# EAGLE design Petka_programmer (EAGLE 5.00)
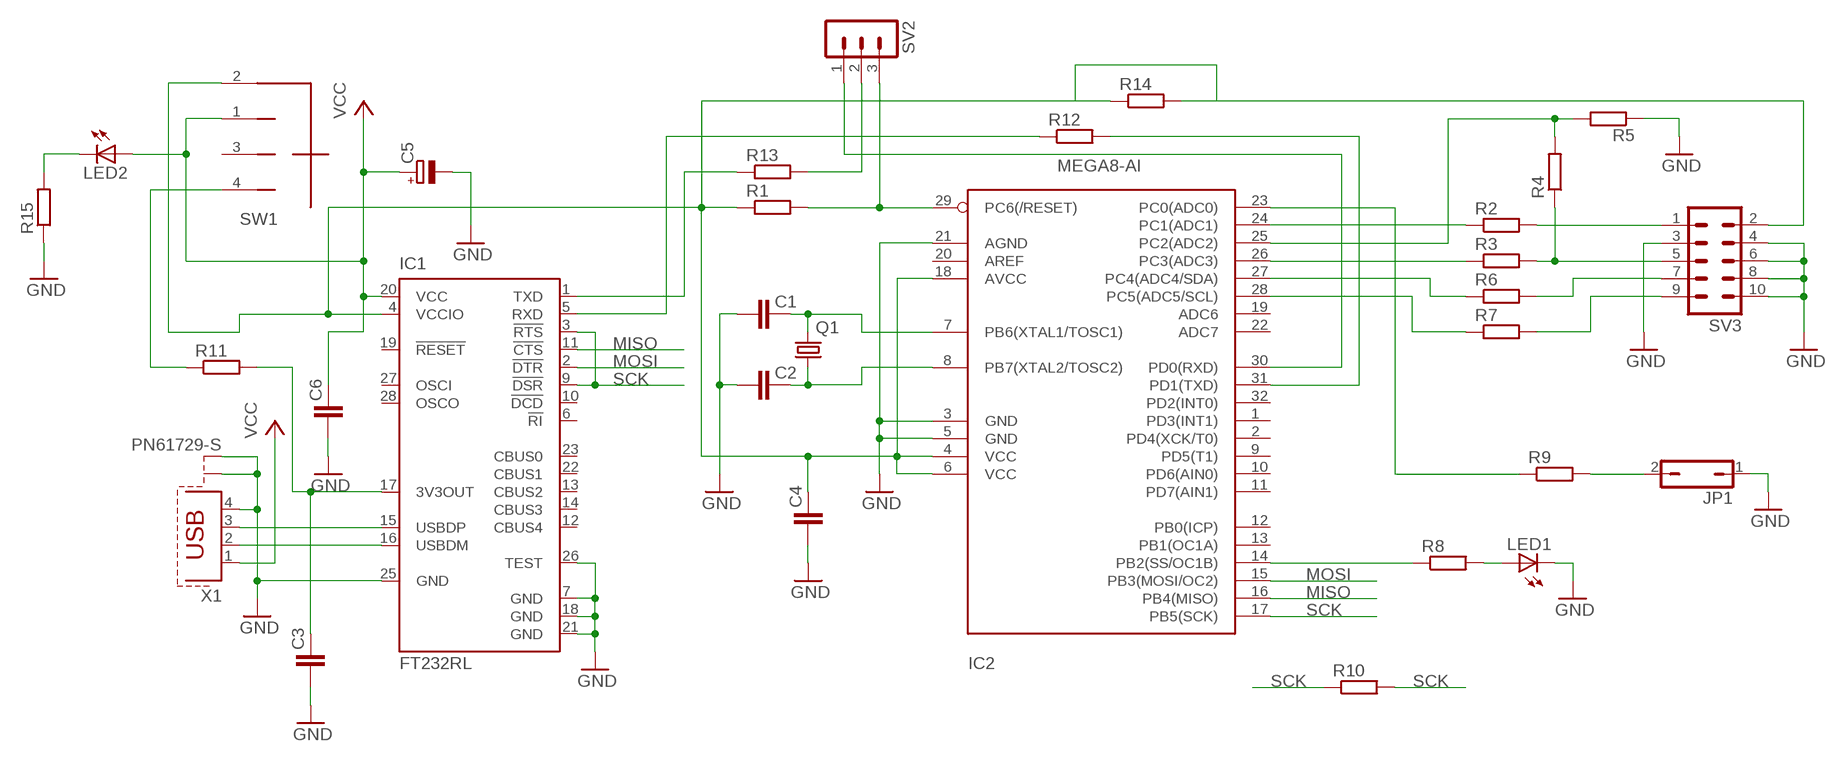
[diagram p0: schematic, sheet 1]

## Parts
C1  C-EUC0805  [C0805]
C2  C-EUC0805  [C0805]
C3  C-EUC0805  [C0805]
C4  C-EUC0805  [C0805]
C5  CPOL-EUSMCD  [SMC_D]
C6  C-EUC0805  [C0805]
IC1  FT232RL  [SSOP28]
IC2  MEGA8-AI  [TQFP32-08]
JP1  JP1Q  [JP1]
LED1  LEDCHIPLED_0805  [CHIPLED_0805]
LED2  LEDCHIPLED_0805  [CHIPLED_0805]
Q1  CRYSTALHC49S  [HC49/S]
R1  R-EU_R0805  [R0805]
R2  R-EU_R0805  [R0805]
R3  R-EU_R0805  [R0805]
R4  R-EU_R0805  [R0805]
R5  R-EU_R0805  [R0805]
R6  R-EU_R0805  [R0805]
R7  R-EU_R0805  [R0805]
R8  R-EU_R0805  [R0805]
R9  R-EU_R0805  [R0805]
R10  R-EU_R0805  [R0805]
R11  R-EU_R0805  [R0805]
R12  R-EU_R0805  [R0805]
R13  R-EU_R0805  [R0805]
R14  R-EU_R0805  [R0805]
R15  R-EU_R0805  [R0805]
SV2  MA03-1  [MA03-1]
SV3  MA05-2  [MA05-2]
SW1  SWITCH1  [SWITCH1]
X1  PN61729-S  [PN61729-S]

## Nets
GND: C1.1 C2.1 C3.1 C4.1 C5.- C6.1 IC1.7(GND) IC1.18(GND) IC1.21(GND) IC1.25(GND) IC1.26(TEST) IC2.3(GND) IC2.5(GND) IC2.21(AGND) JP1.1 LED1.C R5.1 R15.1 SV3.3 SV3.4 SV3.6 SV3.8 SV3.10 X1.4 X1.S1 X1.S2
MISO: IC1.11(!CTS) IC2.16(PB4(MISO))
MOSI: IC1.2(!DTR) IC2.15(PB3(MOSI/OC2))
N$1: LED2.C R15.2
N$2: IC2.29(PC6(/RESET)) R1.2 SV2.3
N$3: IC1.1(TXD) R13.1
N$4: IC2.30(PD0(RXD)) SV2.1
N$5: IC1.5(RXD) R12.1
N$6: C2.2 IC2.8(PB7(XTAL2/TOSC2)) Q1.1
N$7: C1.2 IC2.7(PB6(XTAL1/TOSC1)) Q1.2
N$8: IC1.16(USBDM) X1.2
N$9: IC1.15(USBDP) X1.3
N$10: R11.1 SW1.4
N$11: R2.2 SV3.1
N$12: IC2.24(PC1(ADC1)) R2.1
N$13: IC2.25(PC2(ADC2)) R4.2 R5.2
N$14: R3.2 R4.1 SV3.5
N$15: IC2.26(PC3(ADC3)) R3.1
N$16: R7.2 SV3.9
N$17: R6.2 SV3.7
N$18: IC2.27(PC4(ADC4/SDA)) R6.1
N$19: IC2.28(PC5(ADC5/SCL)) R7.1
N$20: IC2.14(PB2(SS/OC1B)) R8.1
N$21: LED1.A R8.2
N$22: IC2.23(PC0(ADC0)) R9.1
N$23: JP1.2 R9.2
N$24: C3.2 IC1.17(3V3OUT) R11.2
N$25: IC2.31(PD1(TXD)) R12.2
N$26: C4.2 IC1.4(VCCIO) IC2.4(VCC) IC2.6(VCC) IC2.18(AVCC) R1.1 R14.1 R14.2 SV3.2 SW1.2
N$28: R13.2 SV2.2
SCK: IC1.3(!RTS) IC1.9(!DSR) IC2.17(PB5(SCK)) R10.1 R10.2
VCC: C5.+ C6.2 IC1.20(VCC) LED2.A SW1.1 X1.1
Unconnected: IC1.6(!RI) IC1.10(!DCD) IC1.12(CBUS4) IC1.13(CBUS2) IC1.14(CBUS3) IC1.19(!RESET) IC1.22(CBUS1) IC1.23(CBUS0) IC1.27(OSCI) IC1.28(OSCO) IC2.1(PD3(INT1)) IC2.2(PD4(XCK/T0)) IC2.9(PD5(T1)) IC2.10(PD6(AIN0)) IC2.11(PD7(AIN1)) IC2.12(PB0(ICP)) IC2.13(PB1(OC1A)) IC2.19(ADC6) IC2.20(AREF) IC2.22(ADC7) IC2.32(PD2(INT0)) SW1.3

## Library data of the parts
C1-C4 C6 = rcl:C-EU: CAPACITOR, European symbol
C5 = rcl:CPOL-EU: POLARIZED CAPACITOR, European symbol
IC1 = ftdichip:FT232R: Source: http://www.ftdichip.com/Documents/DataSheets/DS_FT232R_v104.pdf
IC2 = atmel:MEGA8: MICROCONTROLLER 8 Kbytes FLASH, 1 kbytes SRAM, 512 bytes EEPROM, USART, 6-channel 10 bit ADC, 2-channel 8 bit ADC Pin compatible with Atmega48, ATMega88, ATMega168 Source: avr.lbr
JP1 = jumper:JP1Q: JUMPER
LED1 LED2 = led:LED: LED
Q1 = crystal:CRYSTAL: CRYSTAL
R1-R15 = rcl:R-EU_: RESISTOR, European symbol
SV2 = con-lstb:MA03-1: PIN HEADER
SV3 = con-lstb:MA05-2: PIN HEADER
SW1 = buttons:SWITCH1
X1 = con-berg:PN61729-S: BERG USB connector

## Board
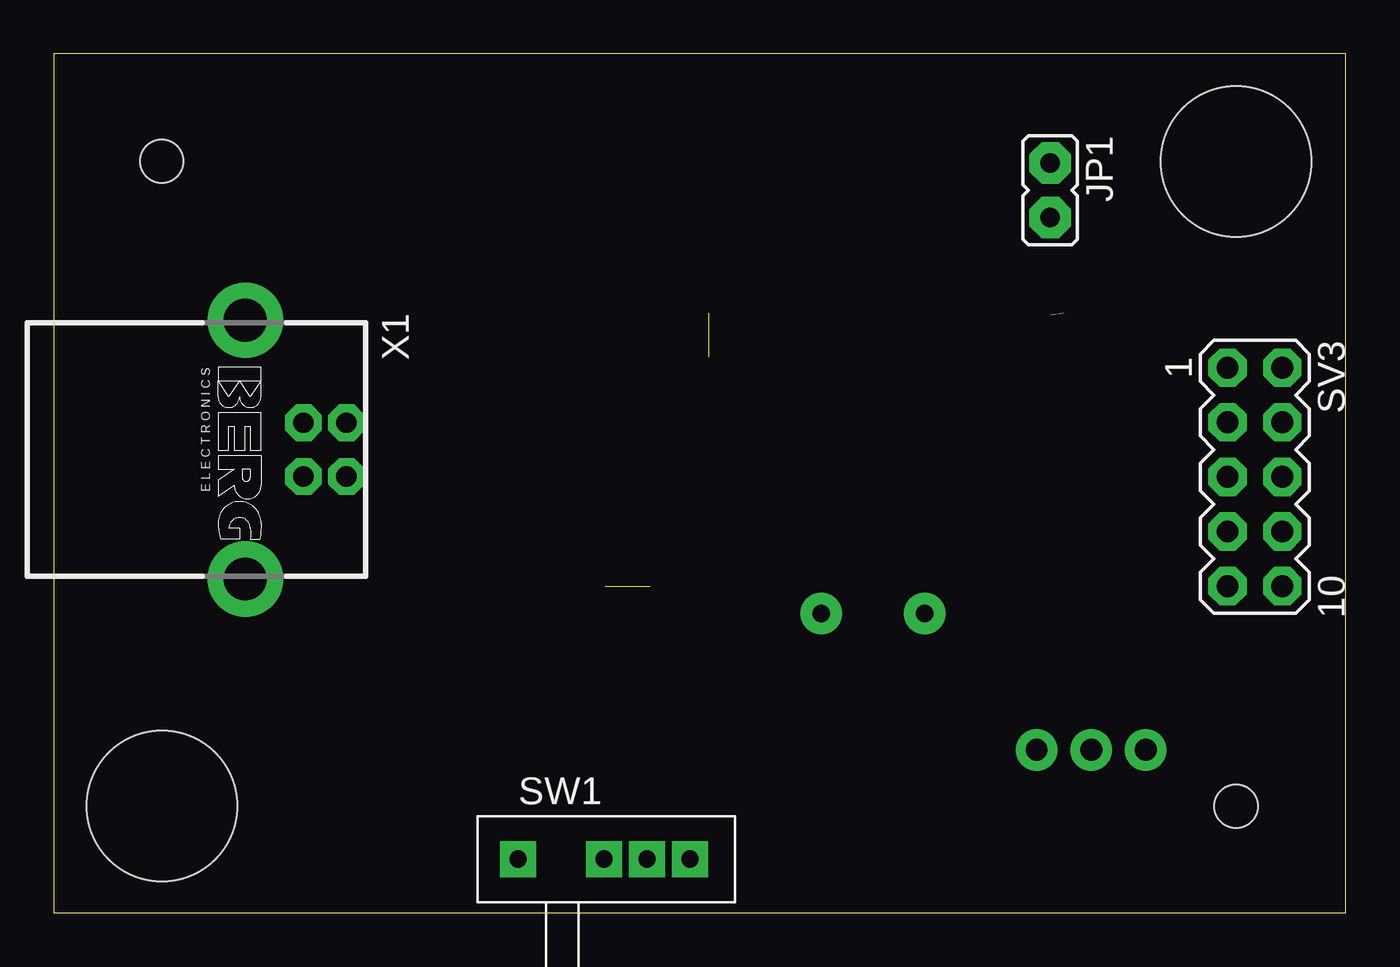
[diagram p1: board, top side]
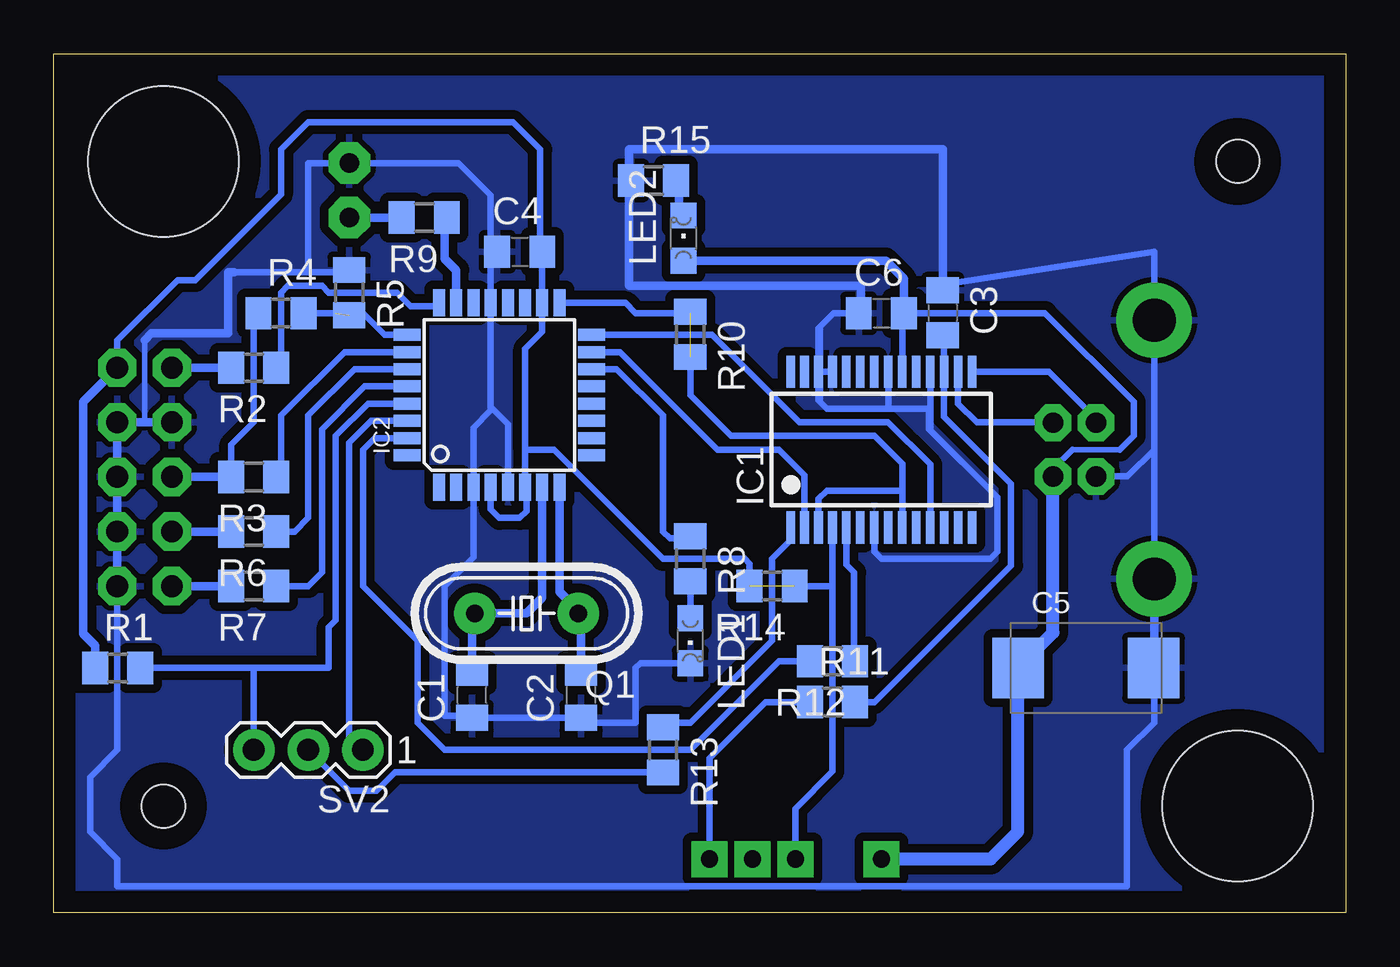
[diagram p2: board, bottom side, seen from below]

Size 60.14 x 39.98 mm. Coordinates in mm from the lower left corner, seen from the top.
Outline: 0,0 60.14,0 60.14,39.98 0,39.98 0,0
Copper layers (1*16): Top 0.035mm / dielectric 1.5mm / Bottom 0.035mm
Design rules "default *": minimum track width 10mil, minimum drill 24mil, track to track 0.3mm, track to pad 0.25mm, pad to pad 0.24mm, via to via 0.3mm, smd to smd 8mil, copper to edge 40mil, drill to drill 8mil, minimum pad ring 10mil, minimum via ring 8mil, stop-mask expansion 4mil, vias tented up to drill 0mil, thermal gap 10mil
Holes 7 mm at 5.03,4.97 55.03,34.97
Holes 2 mm at 5.03,34.97 55.03,4.97

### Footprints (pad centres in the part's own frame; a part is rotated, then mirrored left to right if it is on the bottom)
C0805 = smd 1.2 x 1.5: 1 -1.05,0; 2 1.05,0
SMC_D = smd 2.4 x 2.8: + -3.15,0; - 3.15,0
SSOP28 = smd 0.4 x 1.5: 1 -4.225,-3.625; 2 -3.575,-3.625; 3 -2.925,-3.625; 4 -2.275,-3.625; 5 -1.625,-3.625; 6 -0.975,-3.625; 7 -0.325,-3.625; 8 0.325,-3.625; 9 0.975,-3.625; 10 1.625,-3.625; 11 2.275,-3.625; 12 2.925,-3.625; 13 3.575,-3.625; 14 4.225,-3.625; 15 4.225,3.625; 16 3.575,3.625; 17 2.925,3.625; 18 2.275,3.625; 19 1.625,3.625; 20 0.975,3.625; 21 0.325,3.625; 22 -0.325,3.625; 23 -0.975,3.625; 24 -1.625,3.625; 25 -2.275,3.625; 26 -2.925,3.625; 27 -3.575,3.625; 28 -4.225,3.625
TQFP32-08 = smd 1.27 x 0.559: 1 -4.293,2.8; 2 -4.293,2; 3 -4.293,1.2; 4 -4.293,0.4; 5 -4.293,-0.4; 6 -4.293,-1.2; 7 -4.293,-2; 8 -4.293,-2.8; 17 4.293,-2.8; 18 4.293,-2; 19 4.293,-1.2; 20 4.293,-0.4; 21 4.293,0.4; 22 4.293,1.2; 23 4.293,2; 24 4.293,2.8 | smd 0.559 x 1.27: 9 -2.8,-4.293; 10 -2,-4.293; 11 -1.2,-4.293; 12 -0.4,-4.293; 13 0.4,-4.293; 14 1.2,-4.293; 15 2,-4.293; 16 2.8,-4.293; 25 2.8,4.293; 26 2,4.293; 27 1.2,4.293; 28 0.4,4.293; 29 -0.4,4.293; 30 -1.2,4.293; 31 -2,4.293; 32 -2.8,4.293
JP1 = drill 0.914 pad 1.93 octagon: 1 0,-1.27; 2 0,1.27
CHIPLED_0805 = smd 1.2 x 1.2: A 0,-1.05; C 0,1.05
HC49/S = drill 0.813 pad 1.93 round: 1 -2.413,0; 2 2.413,0
R0805 = smd 1.2 x 1.5: 1 -1.05,0; 2 1.05,0
MA03-1 = drill 1.016 pad 1.93 round: 1 -2.54,0; 2 0,0; 3 2.54,0
MA05-2 = drill 1.016 pad 1.778 octagon: 1 -5.08,-1.27; 2 -5.08,1.27; 3 -2.54,-1.27; 4 -2.54,1.27; 5 0,-1.27; 6 0,1.27; 7 2.54,-1.27; 8 2.54,1.27; 9 5.08,-1.27; 10 5.08,1.27
SWITCH1 = drill 0.8 pad 1.676 square: 1 0,0; 2 4,0; 3 6,0; 4 8,0
PN61729-S = drill 0.95 pad 1.7 octagon: 1 1.25,4.71; 2 -1.25,4.71; 3 -1.25,2.71; 4 1.25,2.71 | drill 2 pad 3.5 round: S1 -6.02,0; S2 6.02,0

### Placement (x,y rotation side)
C1  40.67,10.13 90 bottom
C2  35.59,10.13 90 bottom
C3  18.76,27.93 270 bottom
C4  38.45,30.77 0 bottom
C5  12.09,11.4 0 bottom
C6  21.62,27.91 0 bottom
IC1  21.62,21.56 0 bottom
IC2  39.4,24.1 90 bottom
JP1  46.38,33.62 180 top
LED1  30.51,12.67 180 bottom
LED2  30.83,31.4 0 bottom
Q1  38.13,13.94 180 bottom
R1  57.16,11.4 0 bottom
R2  50.83,25.37 180 bottom
R3  50.83,20.29 180 bottom
R4  49.56,27.91 0 bottom
R5  46.38,28.86 270 bottom
R6  50.83,17.75 180 bottom
R7  50.83,15.21 180 bottom
R8  30.51,16.48 270 bottom
R9  42.89,32.35 180 bottom
R10  30.51,26.92 270 bottom
R11  23.89,9.81 0 bottom
R12  23.89,11.72 180 bottom
R13  31.78,7.59 270 bottom
R14  26.7,15.21 180 bottom
R15  32.22,34.08 0 bottom
SV2  48.29,7.59 180 bottom
SV3  55.91,20.29 270 top
SW1  21.62,2.51 0 top
X1  8.92,21.56 270 top

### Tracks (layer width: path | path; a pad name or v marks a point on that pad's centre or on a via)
GND
  Bottom 0.254: 55.91,22.83 55.91,26.64
  Bottom 0.305: 46.16,29.91 R5.1 46.38,29.81 48.29,29.81 | 39.8,23.46 39.8,23.38 40.6,22.58 IC2.3 40.6,16.55 41.94,15.21 41.94,9.18 40.67,9.18 C1.1 35.69,9.08 35.59,9.18 C2.1 35.59,8.86 33.05,8.86 33.05,11.4 32.83,11.62 LED1.C | 39.8,23.46 IC2.21 39.8,30.45 | 39.8,23.46 39.72,23.46 39,22.75 IC2.5 | 39.8,30.45 39.8,33.39 41.3,34.89 JP1.1 48.29,34.89 48.29,29.81 | 24.16,23.46 21.3,23.46 | IC1.26 24.55,23.85 24.48,23.78 | IC1.26 24.5,25.18 24.49,25.19 24.49,25.18 IC1.25 | IC1.21 21.3,23.47 21.3,23.46 | IC1.26 24.55,27.21 24.48,27.27 | 39.8,30.45 39.4,30.45 39.5,30.55 C4.1 | 21.3,23.46 19.4,23.46 | 19.35,23.52 IC1.18 | 19.4,23.46 19.35,23.52 | 19.35,23.52 19.35,22.46 16.22,19.34 | IC1.7 21.95,16.8 21.62,16.48 16.54,16.48 16.22,16.8 16.22,19.34 | X1.4 10.17,20.31 8.92,21.56 8.92,27.91 | C3.1 18.98,29.28 19.08,29.18 8.92,30.77 8.92,27.91 | 8.92,27.91 X1.S1 X1.S2 | 51.73,29.81 48.29,29.81 | 16.22,19.34 19.4,22.51 19.4,23.46 | 24.16,23.46 19.4,23.46 | 24.48,23.78 24.16,23.46 | 24.48,27.27 24.48,23.78 | 24.48,27.27 23.84,27.91 C6.1 | 8.92,15.21 8.92,27.91 | 8.92,12.04 8.92,8.86 10.19,7.59 10.19,1.24 57.18,1.24 57.18,2.51 58.45,3.78 58.45,6.32 57.18,7.59 SV3.10
  Bottom 0.406: SV3.4 55.91,22.83 | SV3.4 SV3.6 SV3.8 SV3.10 | SV3.4 SV3.3 | C5.- 9.55,11.4 8.92,12.04 8.92,15.21 | 51.73,29.81 52.03,29.81 52.03,26.97 55.59,26.97 55.91,26.64 | 33.37,33.94 33.37,29.18 22.57,29.18 22.57,27.91 C6.1 | 19.08,29.18 18.76,29.18 18.76,35.53 33.37,35.53 33.37,33.94 | 33.37,33.94 33.37,34.08 R15.1
  Bottom 0.61: 8.92,15.21 X1.S2
  pour Bottom (isolate 0.406): 0.03,-0.03 0.03,39.97 60.03,39.97 60.03,-0.03
MISO
  Bottom 0.305: IC2.16 29.5,26.9 25.43,22.83 21.3,22.83 19.35,20.87 IC1.11
MOSI
  Bottom 0.305: IC2.15 33.78,26.1 29.24,21.56 26.38,21.56 25.2,20.37 IC1.2
N$1
  Bottom 0.406: R15.2 31.03,34.08 31.03,32.45 LED2.C
N$2
  Bottom 0.305: IC2.29 45.52,23.7 47.02,22.2 47.02,13.62 47.34,13.31 47.34,11.4 R1.2 50.83,11.4 SV2.3
N$3
  Bottom 0.305: R13.1 31.78,8.86 30.51,8.86 26.7,12.67 26.7,16.48 25.85,17.33 IC1.1
N$4
  Bottom 0.305: IC2.30 45.36,22.9 46.38,21.88 46.38,8.23 SV2.1
N$5
  Bottom 0.305: IC1.5 23.25,16.2 22.89,15.85 22.89,11.72 R12.1
N$6
  Bottom 0.406: 35.59,13.94 Q1.1 | IC2.8 36.6,14.95 35.59,13.94 | C2.2 35.59,13.94
N$7
  Bottom 0.406: IC2.7 37.4,14.67 38.13,13.94 Q1.2 40.67,13.94 C1.2
N$8
  Bottom 0.305: IC1.16 18.05,23.7 17.18,22.83 13.68,22.83 13.66,22.81 X1.2
N$9
  Bottom 0.305: X1.3 11.48,22.81 11.46,22.83 13.81,25.18 IC1.15
N$10
  Bottom 0.305: SW1.4 29.62,7.21 27.02,9.81 R11.1
N$11
  Bottom 0.406: R2.2 SV3.1
N$12
  Bottom 0.305: 49.56,25.37 49.56,28.86 49.24,29.18 47.66,29.18 47.34,28.86 44.16,28.86 43.53,28.23 42.26,28.23 42.2,28.29 IC2.24
  Bottom 0.406: 49.56,25.37 R2.1
N$13  (1 unrouted)
  Bottom 0.305: R4.2 47.02,27.91 45.75,27.91 44.74,26.9 IC2.25
N$14
  Bottom 0.305: R3.2 51.88,21.78 50.83,22.83 50.83,27.91 R4.1
  Bottom 0.406: R3.2 SV3.5
N$15
  Bottom 0.305: IC2.26 46.61,26.1 49.56,23.15 49.56,20.29
  Bottom 0.406: R3.1 49.56,20.29
N$16
  Bottom 0.406: R7.2 SV3.9
N$17
  Bottom 0.406: R6.2 SV3.7
N$18
  Bottom 0.305: IC2.27 46.14,25.3 48.29,23.15 48.29,18.38 48.93,17.75 R6.1
N$19
  Bottom 0.305: IC2.28 45.67,24.5 47.66,22.51 47.66,15.85 48.29,15.21 R7.1
N$20
  Bottom 0.305: IC2.14 33.93,25.3 31.78,23.15 31.78,17.75 31.46,17.43 30.51,17.43 R8.1
N$21
  Bottom 0.305: LED1.A R8.2
N$22
  Bottom 0.406: IC2.23 41.4,29.91 41.94,30.45 41.94,31.72 R9.1
N$23
  Bottom 0.406: R9.2 JP1.2
N$24
  Bottom 0.305: C3.2 18.76,27.27 18.7,27.21 IC1.17 18.7,23.08 15.59,19.97 | R11.2 21.94,9.81 15.59,16.16 15.59,19.97 | 15.59,19.97 16.54,20.92
N$25
  Bottom 0.305: IC2.31 45.21,22.1 45.75,21.56 45.75,15.21 43.21,12.67 43.21,8.86 41.94,7.59 30.51,7.59 26.38,11.72 R12.2 24.8,11.72
N$26  (1 unrouted)
  Bottom 0.305: IC2.4 39.8,18.79 39.4,18.38 38.45,18.38 38.13,18.7 38.13,19.65 38.2,19.72 IC2.6 38.2,21.56 | 38.2,21.56 38.2,26.25 37.4,27.05 | 37.4,27.05 IC2.18 | 37.4,27.05 37.4,30.67 37.5,30.77 | SW1.2 25.62,4.86 23.89,6.58 23.89,15.21 | 23.89,15.21 IC1.4 | 37.5,30.77 C4.2 | 37.5,30.77 37.5,35.53 38.77,36.8 48.29,36.8 49.56,35.53 49.56,33.44 53.55,29.45 54.37,29.45 57.18,26.64 SV3.2 | 23.89,15.21 24.16,15.21 | 23.89,15.21 R14.1 | R14.2 27.75,16.26 27.97,16.48 31.78,16.48 36.86,21.56 38.2,21.56
  Bottom 0.406: R1.1 58.21,12.43 58.77,12.99 58.77,23.78 SV3.2
N$28
  Bottom 0.305: R13.2 44.26,6.54 45.12,5.68 46.38,5.68 SV2.2
SCK  (1 unrouted)
  Bottom 0.305: IC2.17 33.53,28.39 33.05,27.91 30.51,27.91 R10.1 | R10.2 30.51,24.1 28.61,22.2 21.94,22.2 20.64,20.9 IC1.9 20.64,19.63 20.67,19.65 24.16,19.65 24.55,19.27 IC1.3
VCC
  Bottom 0.254: 12.73,21.56 10.51,21.56
  Bottom 0.305: X1.1 13.63,20.66 12.73,21.56 | 10.51,21.56 9.87,22.2 9.87,23.78 14,27.91 20.35,27.91 | 20.35,27.91 C6.2 | IC1.20 20.64,27.61 20.35,27.91
  Bottom 0.406: LED2.A 21.41,30.35 20.57,29.51 C6.2
  Bottom 0.61: X1.1 13.63,13.04 15.27,11.4 | SW1.1 16.54,2.51 15.27,3.78 15.27,11.4 | 15.27,11.4 C5.+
